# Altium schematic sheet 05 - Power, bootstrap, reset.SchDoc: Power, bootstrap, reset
size A3; PageSetup: Record=PageOptions¦CenterHorizontal=True¦CenterVertical=True¦PrintScale=0.70¦XCorrection=1.00¦YCorrection=1.00¦PrintKind=0¦BorderSize=5000000¦LeftOffset=0¦BottomOffset=0¦Orientation=2¦PaperLength=4200¦PaperWidth=2970¦Scale=100¦PaperSource=7¦PrintQuality=600¦MediaType=1¦DitherType=10¦PaperKind=A4¦PrintScaleMode=1; Author: Juan Anzola; SheetNumber: 5; SheetTotal: 17
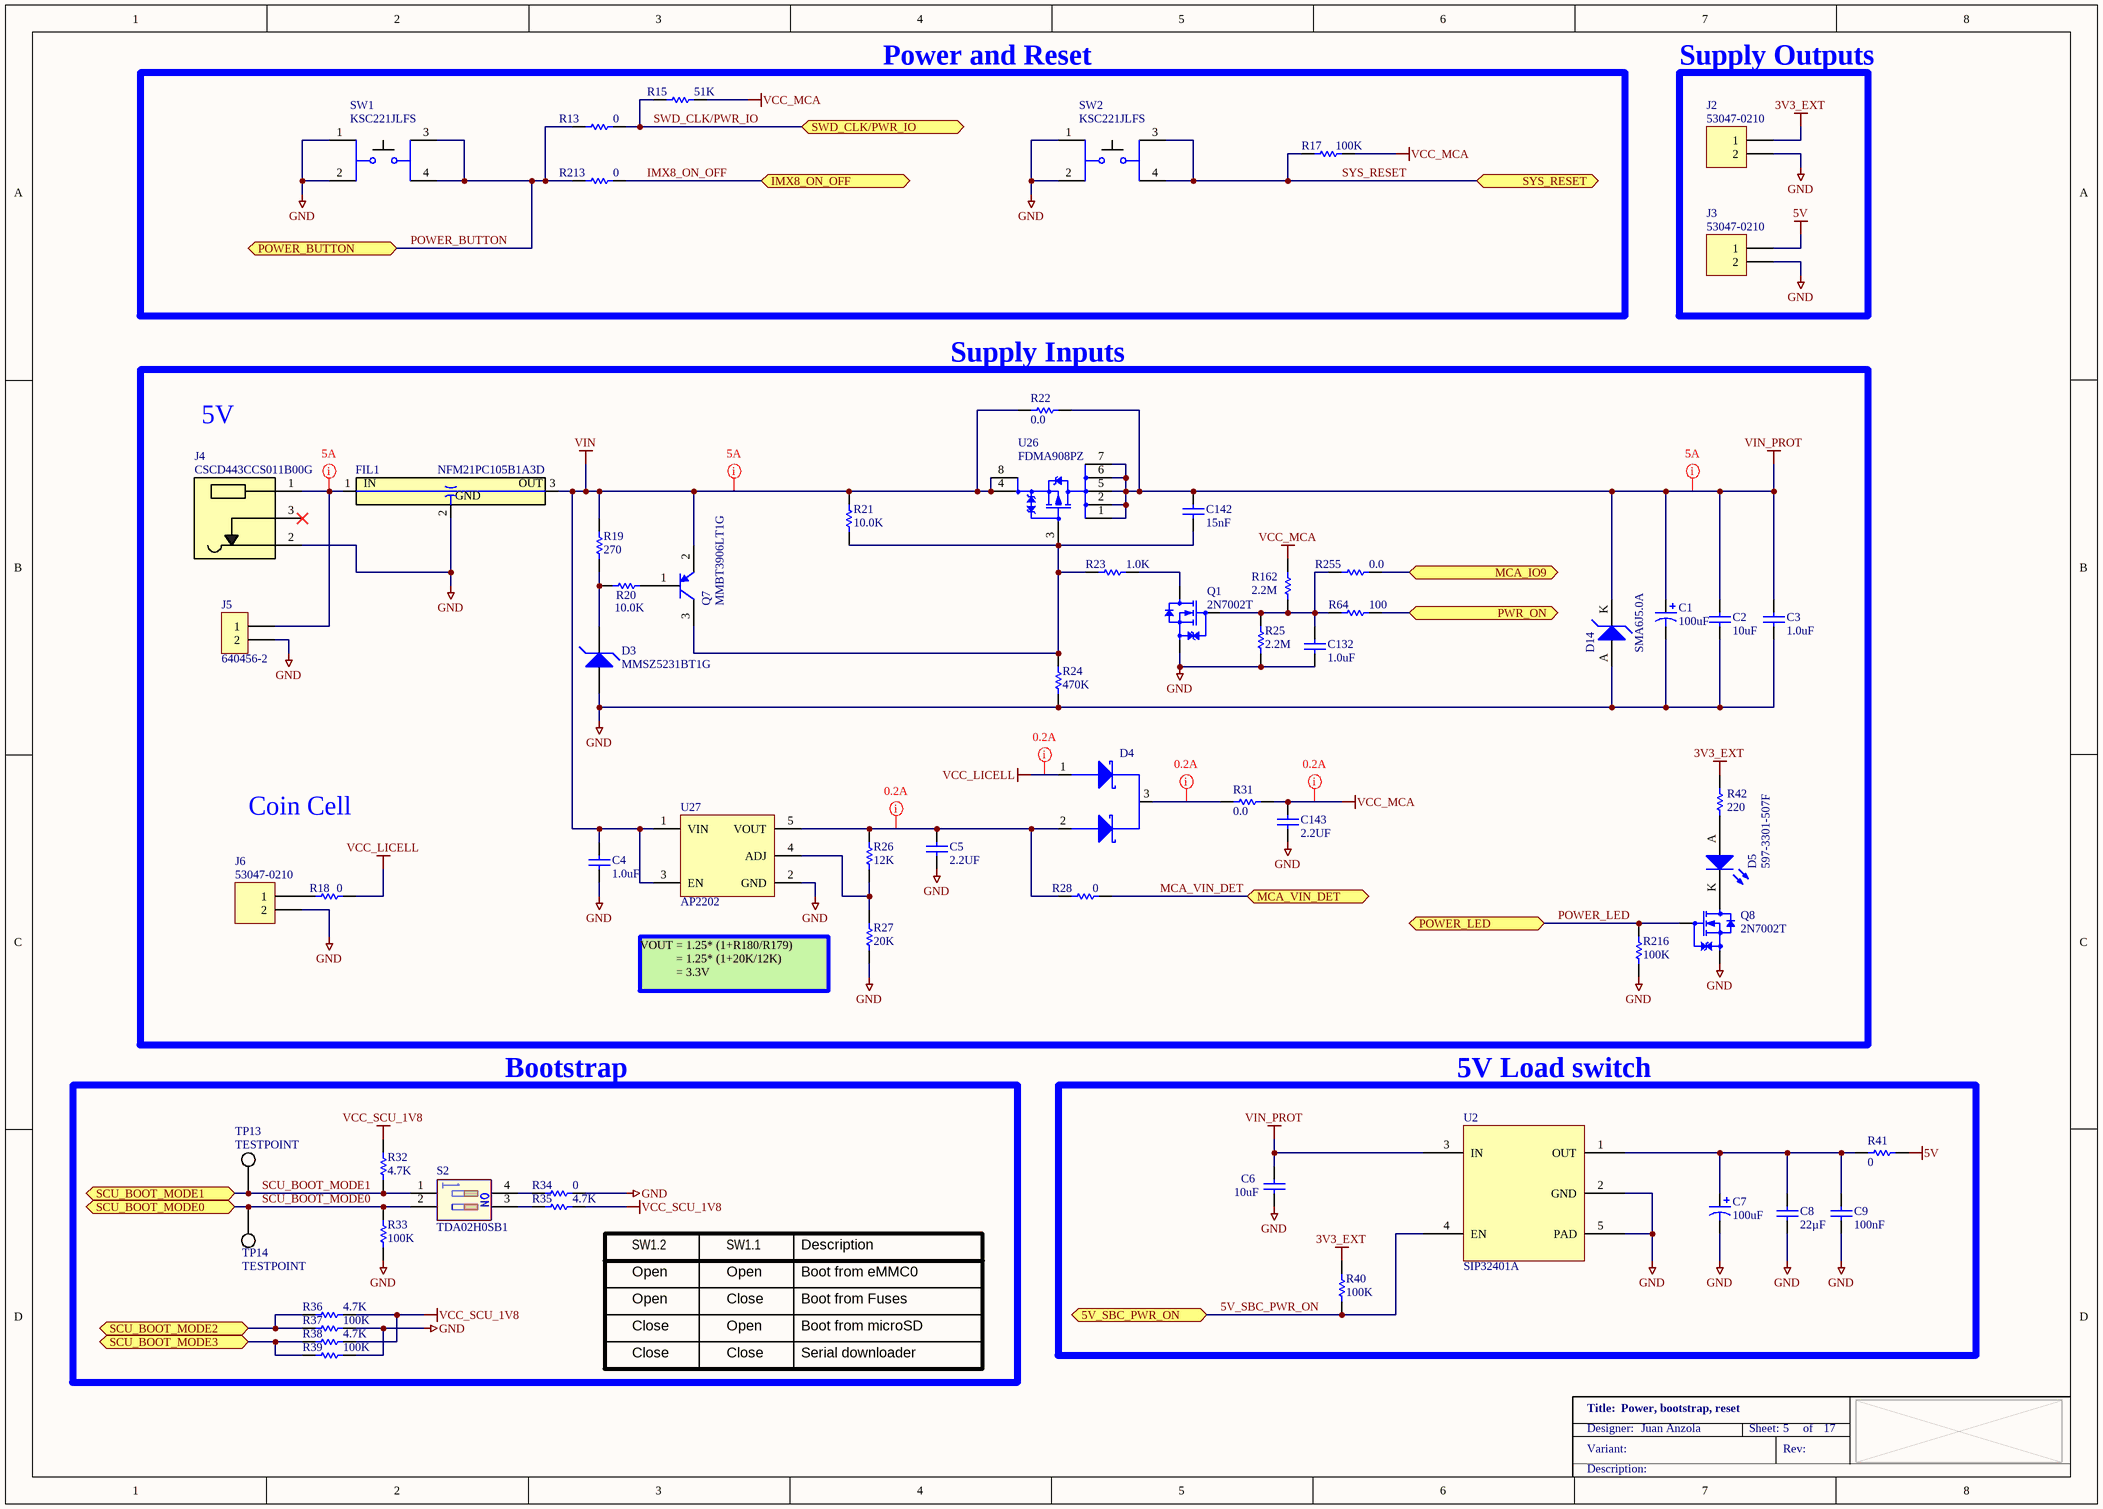
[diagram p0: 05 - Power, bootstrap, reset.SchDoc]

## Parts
C1  100uF  [CAPMP3216X120N]
C2  10uF  [CAPC1005X55N]
C3  1.0uF  [CAPC1005X55N]
C4  1.0uF  [CAPC1005X55L]
C5  2.2UF  [CAPC1608X90N]
C6  10uF  [CAPC1005X55N]
C7  100uF  [CAPMP3216X120N]
C8  22µF  [CAPC1608X90N]
C9  100nF  [CAPC1005X55N]
C132  1.0uF  [CAPC1005X55N]
C142  15nF  [CAPC1005X55N]
C143  2.2UF  [CAPC1608X90N]
D3  MMSZ5231BT1G  [SOD3716X135N]
D4  BAT54CWT1G  [SOT65P210X100-3AN]  (value not drawn)
D5  597-3301-507F  [LEDM3020X130N]
D14  SMA6J5.0A  [DIOM5127X229AN]
FIL1  NFM21PC105B1A3D  [FIL_NFM21P]
J2  Manufacturer_Part_Number: 53047-0210  [MOLEX_53047-0210]  (hidden comment: 1x2P)
J3  Manufacturer_Part_Number: 53047-0210  [MOLEX_53047-0210]  (hidden comment: 1x2P)
J4  CSCD443CCS011B00G  [conn_CSCD443CCS011B00G]
J5  640456-2  [TE_640456-2]
J6  Manufacturer_Part_Number: 53047-0210  [MOLEX_53047-0210]  (hidden comment: 1x2P)
Q1  2N7002T  [SOTFL50P160X80_GSD-3N]
Q7  MMBT3906LT1G  [SOT95P240X110-3N]
Q8  2N7002T  [SOTFL50P160X80_GSD-3N]
R13  0  [RESC1005X40N]
R15  51K  [RESC1005X40N]
R17  100K  [RESC1005X40N]
R18  0  [RESC1005X40N]
R19  270  [RESC2013X70N]
R20  10.0K  [RESC1005X40N]
R21  10.0K  [RESC1005X40N]
R22  0.0  [RESC2013X70N]
R23  1.0K  [RESC1005X40N]
R24  470K  [RESC1005X40N]
R25  2.2M  [RESC1005X40N]
R26  12K  [RESC1609X55N]
R27  20K  [RESC1609X55N]
R28  0  [RESC1005X40N]
R31  0.0  [RESC2013X70N]
R32  4.7K  [RESC1005X40N]
R33  100K  [RESC1005X40N]
R34  0  [RESC1005X40N]
R35  4.7K  [RESC1005X40N]
R36  4.7K  [RESC1005X40N]
R37  100K  [RESC1005X40N]
R38  4.7K  [RESC1005X40N]
R39  100K  [RESC1005X40N]
R40  100K  [RESC1005X40N]
R41  0  [RESC1609X55N]
R42  220  [RESC1005X40N]
R64  100  [RESC1005X40N]
R162  2.2M  [RESC1005X40N]
R213  0  [RESC1005X40N]
R216  100K  [RESC1005X40N]
R255  0.0  [RESC2013X70N]
S2  TDA02H0SB1  [SW_TDA02]
SW1  KSC221JLFS  [SW_KSC221J]
SW2  KSC221JLFS  [SW_KSC221J]
TP13  TESTPOINT  [TP0762]  (no BOM)
TP14  TESTPOINT  [TP0762]  (no BOM)
U2  SIP32401A  [SON50P120X160X60-5T55X91N]
U26  FDMA908PZ  [FAIRCHILD_MICROFET_2X2]
U27  AP2202  [SOT95P280X145-5N]

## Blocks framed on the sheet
Power and Reset: R13 R15 R17 R213 SW1 SW2
Supply Outputs: J2 J3
Supply Inputs: C1-C5 C132 C142 C143 D3-D5 D14 FIL1 J4-J6 Q1 Q7 Q8 R18-R28 R31 R42 R64 R162 R216 R255 U26 U27
Bootstrap: R32-R39 S2 TP13 TP14
5V Load switch: C6-C9 R40 R41 U2

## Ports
5V_SBC_PWR_ON (bidir), IMX8_ON_OFF (bidir), MCA_IO9 (bidir), MCA_VIN_DET (bidir), POWER_BUTTON (bidir), POWER_LED (bidir), PWR_ON (bidir), SCU_BOOT_MODE0 (bidir), SCU_BOOT_MODE1 (bidir), SCU_BOOT_MODE2 (bidir), SCU_BOOT_MODE3 (bidir), SWD_CLK/PWR_IO (bidir), SYS_RESET (bidir)

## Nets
3V3_EXT: J2.1 R40.1 R42.2
5V: J3.1 R41.2
GND: C1.2 C2.1 C3.1 C4.1 C5.1 C6.1 C7.2 C8.1 C9.1 C132.1 C143.1 D3.A D14.A FIL1.2(GND) J2.2 J3.2 J4.2 J5.2 J6.2 Q1.S Q8.S R24.1 R25.1 R27.1 R33.1 R34.2 R37.1 R39.1 R216.2 SW1.1 SW1.2 SW2.1 SW2.2 U2.2(GND) U2.5(PAD) U27.2(GND)
VCC_LICELL: D4.1 R18.1
VCC_MCA: C143.2 R15.2 R17.2 R31.2 R162.2
VCC_SCU_1V8: R32.2 R35.2 R36.1 R38.1
VIN: C4.2 FIL1.3(Output) Q7.2(E) R19.2 R21.2 R22.1 U26.4(S) U26.8(S) U27.1(VIN) U27.3(EN)
VIN_PROT: C1.1 C2.2 C3.2 C6.2 C142.2 D14.K R22.2 U2.3(IN) U26.1(D) U26.2(D) U26.5(D) U26.6(D) U26.7(D)
5V_SBC_PWR_ON: R40.2 U2.4(EN) ; port 5V_SBC_PWR_ON
IMX8_ON_OFF: R213.2 ; port IMX8_ON_OFF
MCA_IO9: R255.2 ; port MCA_IO9
MCA_VIN_DET: R28.2 ; port MCA_VIN_DET
POWER_BUTTON: R13.1 R213.1 SW1.3 SW1.4 ; port POWER_BUTTON
POWER_LED: Q8.G R216.1 ; port POWER_LED
PWR_ON: R64.2 ; port PWR_ON
SCU_BOOT_MODE0: R33.2 S2.2(A2) TP14.1 ; port SCU_BOOT_MODE0
SCU_BOOT_MODE1: R32.1 S2.1(A1) TP13.1 ; port SCU_BOOT_MODE1
SCU_BOOT_MODE2: R36.2 R37.2 ; port SCU_BOOT_MODE2
SCU_BOOT_MODE3: R38.2 R39.2 ; port SCU_BOOT_MODE3
SWD_CLK/PWR_IO: R13.2 R15.1 ; port SWD_CLK/PWR_IO
SYS_RESET: R17.1 SW2.3 SW2.4 ; port SYS_RESET
NetC5_2: C5.2 D4.2 R26.2 R28.1 U27.5(VOUT)
NetC7_1: C7.1 C8.2 C9.2 R41.1 U2.1(OUT)
NetC132_2: C132.2 Q1.G R25.2 R64.1 R162.1 R255.1
NetC142_1: C142.1 Q7.3(C) R21.1 R23.1 R24.2 U26.3(G)
NetD3_K: D3.K R19.1 R20.1
NetD4_3: D4.3 R31.1
NetD5_A: D5.A R42.1
NetD5_K: D5.K Q8.D
NetFIL1_1: FIL1.1(Input) J4.1 J5.1
NetJ6_1: J6.1 R18.2
NetQ1_D: Q1.D R23.2
NetQ7_1: Q7.1(B) R20.2
NetR26_1: R26.1 R27.2 U27.4(ADJ)
NetR34_1: R34.1 S2.4(B1)
NetR35_1: R35.1 S2.3(B2)

Not connected (* = marked no-connect by the designer): J4 3*

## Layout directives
net class 0.2A: NetC5_2, NetD4_3, VCC_LICELL, VCC_MCA
net class 5A: NetFIL1_1, VIN, VIN_PROT

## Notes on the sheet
- 5V
- Coin Cell
- VOUT = 1.25* (1+R180/R179)
  = 1.25* (1+20K/12K)
  = 3.3V
- SW1.2
- SW1.1
- Description
- Open
- Close
- Boot from eMMC0
- Boot from Fuses
- Boot from microSD
- Serial downloader

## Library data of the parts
C1 C7 = 1001196: CAP TANT 100UF 6.3V 20% 1206; Part_Type: Capacitor; Manufacturer: Rohm; Manufacturer_Part_Number: TCTAL0J107M8R; Digi_PN: 14050490; Component_Life_Cycle_State: Reviewed; Area: 8.01; Project: CCWMX6_SBC board
C2 C6 = 1001168: CAP CER 10UF 10V 20% X5R 0402; Part_Type: Capacitor; Manufacturer: Samsung; Manufacturer_Part_Number: CL05A106MP5NUNC; Digi_PN: 14050689; Component_Life_Cycle_State: Reviewed; Area: 0.95; Project: CCWMX6_SBC board
C3 C132 = 1001167: CAP CER 1UF 10V 10% X5R 0402; Part_Type: Capacitor; Manufacturer: Murata; Manufacturer_Part_Number: GRM155R61A105KE15D; Digi_PN: 14050399; Component_Life_Cycle_State: Reviewed; Area: 0,95; Project: CCWMX6_SBC board
C4 = 1000073: CAP CER 1UF 6.3V 20% X5R 0402; Part_Type: Capacitor; Manufacturer: Murata; Manufacturer_Part_Number: GRM155R60J105ME19D; Digi_PN: 14050543; Component_Life_Cycle_State: Proven; Area: 0.95; Project: Adjustable Foundation
C5 C143 = 1001303: CAP CER 2.2UF 16V 10% X5R 0603; Part_Type: Capacitor; Manufacturer: TDK Corporation; Manufacturer_Part_Number: C1608X5R1C225K080AB; Digi_PN: 14050730; Component_Life_Cycle_State: Reviewed; Area: 2,27; Project: Pinnacle
C8 = 1000998: CAP CER 22UF 10V 20% X5R 0603; Part_Type: Capacitor; Manufacturer: Samsung; Manufacturer_Part_Number: CL10A226MP8NUNE; Manufacturer_Alt_1: TDK Corporation; Manufacturer_Alt_1_Part_Number: C1608X5R1A226M080AC; Digi_PN: 14050684; Component_Life_Cycle_State: Reviewed; Area: 2.27; Project: ConnectCore i.MX6 module; Tolerance: 20
C9 = 1000006: CAP 100nF 16V 10% X7R 0402; Part_Type: Capacitor; Manufacturer: Murata; Manufacturer_Part_Number: GRM155R71C104KA88D; Component_Life_Cycle_State: CAD Reviewed; Area: 0.95; Project: KITT; Tolerance: 10; Digi_PN: 14050552
C142 = 1000512: CAP CER 0.015UF 16V 10% X7R 0402; Part_Type: Capacitor; Manufacturer: Murata; Manufacturer_Part_Number: GRM155R71C153KA01D; Digi_PN: 14050713; Component_Life_Cycle_State: CAD Reviewed; Area: 0,95; Project: Cellular Proof of Concept
D3 = 1001494: DIODE ZENER 5.1V 500MW SOD123; Part_Type: Diodes; Manufacturer: On Semiconductor; Digi_PN: 17050700; Component_Life_Cycle_State: Reviewed; Area: 8.28; Project: CCWMX6_SBC board; Note: 17050805 = Digi No. for GE WDNU
D4 = 1000794: DIODE SCHOTTKY 30V 200MA SOT323; Part Number: SDS1920004; Manufacturer: Fairchild Semiconductor; Manufacturer Alt 1: none; Manufacturer Part Num: 0082610201; Part_Type: Diodes; Digi_PN: 17050561; Component_Life_Cycle_State: CAD Reviewed; Area: 7,68; Project: SmartMeter2
D5 = 1001189: LED GREEN 573NM 1208 SMD; Manufacturer: Dialight; Digi_PN: 17050183; Component_Life_Cycle_State: Reviewed; Area: 6; Project: CCWMX6_SBC board; Note: 17050846 = Digi PN for GE WDNU II
D14 = 1002782: SMDIO,TVS UNI-DIR 5V 600W SMA; Part_Type: Diodes; Manufacturer: Vishay Semiconductors; Manufacturer_Part_Number: SMA6J5.0A-M3/5A; Digi_PN: 17000173; Component_Life_Cycle_State: Created; Area: 15.312; Project: DIGI CC8X SOM
FIL1 = 1002768: CAP FEEDTHRU 1UF 20% 10V 0805; Part_Type: Filter; Manufacturer: Murata; Digi_PN: 21000606; Component_Life_Cycle_State: Reviewed; Area: 6.6; Project: DIGI CC8X SOM; Voltage: 10
J2 J3 J6 = 1001136: CONN HEADER 2POS 1.25MM VERT TIN; Part_Type: Connector; Manufacturer: Molex; Component_Life_Cycle_State: Reviewed; Area: 13.6; Project: CCWMX6_SBC board; Digi_PN: 18050343
J4 = 1001105: DC Power Jack; Part_Type: Connector; Manufacturer: Bobbintron Electrical Corp; Digi_PN: 18000302; Component_Life_Cycle_State: Reviewed; Area: 137; Project: CCWMX6_SBC board
J5 = 1002003: CONN HEADER VERT 2POS .100 TIN; Part_Type: Connector; Manufacturer: TE Connectivity; Digi_PN: 18050128; Component_Life_Cycle_State: Created; Area: 29,05; Project: iMX6UL+PMIC
Q1 = 1000715: MOSFET N-CH 60V 115MA SOT-523F; Part_Type: Transistor; Manufacturer: Fairchild Semiconductor; Note: 17050841 = Digi No. for GE WDNU; Digi_PN: 17050797; Component_Life_Cycle_State: CAD Reviewed; Area: 3,06; Project: SmartMeter2
Q7 = 1001204: TRANS GP SS PNP 40V SOT23; Part_Type: IC; Manufacturer: On Semiconductor; Digi_PN: 17050145; Component_Life_Cycle_State: Reviewed; Area: 10.92; Project: CCWMX6_SBC board
Q8 = 1000715: MOSFET N-CH 60V 115MA SOT-523F; Part_Type: Transistor; Manufacturer: Fairchild Semiconductor; Digi_PN: 17050797; Component_Life_Cycle_State: CAD Reviewed; Area: 3.06; Project: SmartMeter2; Note: 17050841 = Digi No. for GE WDNU
R13 R18 R28 R213 = 1000076: RES 0.0 OHM 1/10W 0402 SMD; Part_Type: Resistor; Manufacturer: Panasonic - ECG; Manufacturer_Part_Number: ERJ-2GE0R00X; Component_Life_Cycle_State: Proven; Area: 0.95; Project: Adjustable Foundation; Power_WV_SRF: 10; Digi_PN: 13050387
R15 = 1001313: RES 51K OHM 1/10W 5% 0402 SMD; Part_Type: Resistor; Manufacturer: Panasonic - ECG; Manufacturer_Part_Number: ERJ-2GEJ513X; Component_Life_Cycle_State: Reviewed; Area: 0,95; Power_WV_SRF: 100; Digi_PN: 13000092
R17 R33 R37 R39 = 1000480: RES 100K OHM 1/10W 1% 0402 SMD; Part_Type: Resistor; Manufacturer: Panasonic - ECG; Manufacturer_Part_Number: ERJ-2RKF1003X; Digi_PN: 13051063; Component_Life_Cycle_State: CAD Reviewed; Area: 0,95; Project: KITT; Power_WV_SRF: 100
R19 = 1001323: RES 270 OHM 1/2W 5% 0805 SMD; Part_Type: Resistor; Manufacturer: Panasonic - ECG; Manufacturer_Part_Number: ERJ-P06J271V; Digi_PN: 13051049; Component_Life_Cycle_State: Reviewed; Area: 4.12; Project: Pinnacle; Power_WV_SRF: 500
R20 R21 = 1000537: RES 10.0K OHM 1/10W 1% 0402 SMD; Part_Type: Resistor; Manufacturer: Panasonic - ECG; Manufacturer_Part_Number: ERJ-2RKF1002X; Digi_PN: 13051084; Component_Life_Cycle_State: CAD Reviewed; Area: 0.95; Project: KITT; Power_WV_SRF: 100
R22 R31 R255 = 1001557: RES 0.0 OHM 1/8W JUMP 0805 SMD; Part_Type: Resistor; Manufacturer: Yageo; Manufacturer_Part_Number: RC0805JR-070RL; Note: 13051095 = Digi No. for GE WDNU; Digi_PN: TR00037; Component_Life_Cycle_State: Reviewed; Area: 5.8; Project: WDNU-II; Power_WV_SRF: 125
R23 = 1000079: RES 1.00K OHM 1/10W 1% 0402 SMD; Part_Type: Resistor; Manufacturer: Panasonic - ECG; Manufacturer_Part_Number: ERJ-2RKF1001X; Digi_PN: 13051085; Component_Life_Cycle_State: Proven; Area: 0,95; Project: Adjustable Foundation; Power_WV_SRF: 10
R24 = 1000701: RES 470K OHM 1/10W 1% 0402 SMD; Part_Type: Resistor; Manufacturer: Panasonic - ECG; Manufacturer_Part_Number: ERJ-2RKF4703X; Component_Life_Cycle_State: CAD Reviewed; Area: 0.95; Project: KITT; Power_WV_SRF: 100; Digi_PN: 13051092
R25 = 1001917: RES SMD 2.2M OHM 5% 1/10W 0402; Part_Type: Resistor; Manufacturer: Panasonic - ECG; Manufacturer_Part_Number: ERJ-2GEJ225X; Digi_PN: 13050820; Component_Life_Cycle_State: Reviewed; Area: 2,27; Project: Powerley Energy Bridge; Power_WV_SRF: 0,1
R26 = 1001200: RES 12.0K OHM 1/10W 1% 0603 SMD; Part_Type: Resistor; Manufacturer: Yageo; Manufacturer_Part_Number: RC0603FR-0712KL; Digi_PN: 13050531; Component_Life_Cycle_State: Reviewed; Area: 2,5; Project: LuCoV2; Power_WV_SRF: 100; Tolerance: 1
R27 = 1000142: RES 20K OHM 1/10W 5% 0603 SMD; Part_Type: Resistor; Manufacturer: Panasonic - ECG; Manufacturer_Part_Number: ERJ-3GEYJ203V; Digi_PN: 13050013; Component_Life_Cycle_State: Reviewed; Area: 2,5; Project: Adjustable Foundation; Power_WV_SRF: 100; Tolerance: 5
R32 R35 R36 R38 = 1000038: RES 4.7K OHM 1/10W 5% 0402 SMD; Part_Type: Resistor; Manufacturer: Panasonic - ECG; Manufacturer_Part_Number: ERJ-2GEJ472X; Digi_PN: 13050549; Component_Life_Cycle_State: Proven; Area: 0,95; Project: Adjustable Foundation; Power_WV_SRF: 100; Tolerance: 5
R34 = 1000076: RES 0.0 OHM 1/10W 0402 SMD; Part_Type: Resistor; Manufacturer: Panasonic - ECG; Manufacturer_Part_Number: ERJ-2GE0R00X; Digi_PN: 13050387; Component_Life_Cycle_State: Proven; Area: 0,95; Project: Adjustable Foundation; Power_WV_SRF: 10
R40 R216 = 1000480: RES 100K OHM 1/10W 1% 0402 SMD; Part_Type: Resistor; Manufacturer: Panasonic - ECG; Manufacturer_Part_Number: ERJ-2RKF1003X; Digi_PN: 13051063; Component_Life_Cycle_State: CAD Reviewed; Area: 0.95; Project: KITT; Power_WV_SRF: 100
R41 = 1000208: RES 0.0 OHM 1/10W 0603; Part_Type: Resistor; Manufacturer: Panasonic - ECG; Manufacturer_Part_Number: ERJ-3GEY0R00V; Note: 13051103 = Digi No. for GE WDNU; Digi_PN: 13050568; Component_Life_Cycle_State: Reviewed; Area: 2.5; Project: Adjustable Foundation; Voltage: 75V
R42 = 1001154: RES 220 OHM 1/16W 1% 0402 SMD; Part_Type: Resistor; Manufacturer: Yageo; Manufacturer_Part_Number: RC0402FR-07220RL; Digi_PN: 13050623; Component_Life_Cycle_State: Reviewed; Area: 0.95; Project: CCWMX6_SBC board
R64 = 1000467: RES 100 OHM 1/10W 1% 0402 SMD; Part_Type: Resistor; Manufacturer: Panasonic - ECG; Manufacturer_Part_Number: ERJ-2RKF1000X; Digi_PN: 13051087; Component_Life_Cycle_State: CAD Reviewed; Area: 0,95; Project: KITT
R162 = 1001917: RES SMD 2.2M OHM 5% 1/10W 0402; Part_Type: Resistor; Manufacturer: Panasonic - ECG; Manufacturer_Part_Number: ERJ-2GEJ225X; Digi_PN: 13050820; Component_Life_Cycle_State: Reviewed; Area: 2.27; Project: Powerley Energy Bridge; Power_WV_SRF: 0.1
S2 = 1001500: SWITCH DIP 2POS HALF PITCH 24V; Manufacturer: C&K Components; Note: 22000296 = Digi No. for GE WDNU; Digi_PN: 22000060; Component_Life_Cycle_State: Reviewed; Area: 34,3; Project: CCWMX6_SBC board
SW1 SW2 = 1001124: SWITCH TACTILE SPST-NO 0.05A 32V; Manufacturer: ITT; Digi_PN: 22000059; Component_Life_Cycle_State: Reviewed; Area: 37; Project: CCWMX6_SBC board; Note: 22000295 = Digi No. for GE WDNU
TP13 TP14 = CAD0011: TEST POINT 30MIL PAD SMT; Component_Life_Cycle_State: Reviewed; Area: 0,58; Project: CLC
U2 = 1001857: IC SW W/CTRL SLEW RATE 4TDFN; Manufacturer: Vishay Siliconix; Manufacturer_Part_Number: SIP32401ADNP-T1GE4; Component_Life_Cycle_State: Reviewed; Area: 4.93; Project: CCWMX6_SBC board; Digi_PN: 16052004
U26 = 1001972: MOSFET P-CH 12V 12A 6QFN; Part_Type: Transistor; Manufacturer: Fairchild Semiconductors; Digi_PN: 17050873; Component_Life_Cycle_State: Reviewed; Area: 9; Project: iMX6UL+PMIC
U27 = 1001979: IC REG LDO ADJ 0.15A SOT25; Part_Type: Regulator; Manufacturer: Diodes, Inc.; Manufacturer_Part_Number: AP2202K-ADJTRG1; Digi_PN: 17050874; Component_Life_Cycle_State: Created; Area: 8,9; Project: iMX6UL+PMIC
